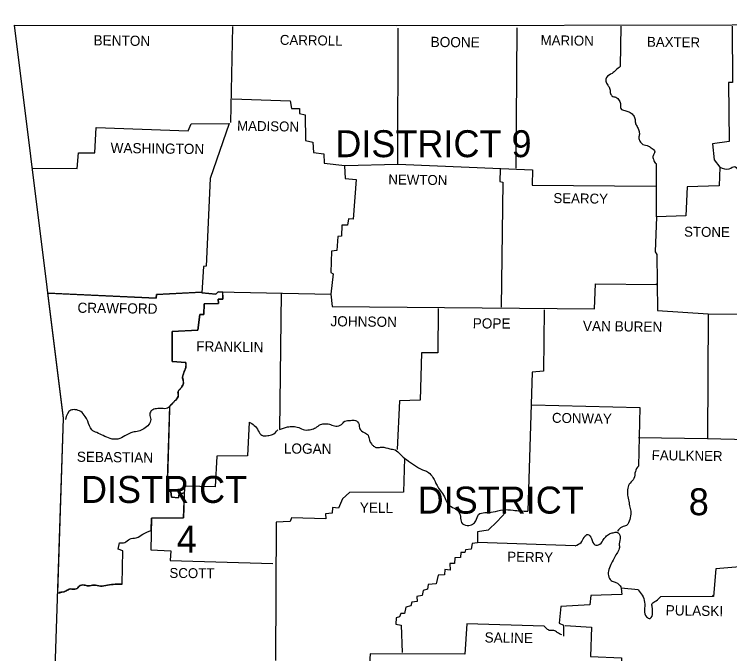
# Model space of a CAD drawing. Extents: x -17668 to 16999, y -17303 to 5867.
# Drawn here: x 1332 to 2998, y 4379 to 5867 of the extents above; entities that cross this region are included whole.
import ezdxf

# ---------------------------------------------------------------- set-up
doc = ezdxf.new("R2010")
doc.units = 0
for name, color, linetype in [('1', 7, 'Continuous'), ('2', 7, 'Continuous'), ('3', 7, 'Continuous'), ('45', 7, 'Continuous')]:
    doc.layers.add(name, color=color, linetype=linetype)

msp = doc.modelspace()

# ---------------------------------------------------------------- linework, layer by layer
at = {"layer": '1'}
for points in [[(1332.2, 5841.4), (2222.1, 5840.9), (3003, 5842.5), (3924.3, 5856.8), (4351.4, 5866.7)], [(1332.2, 5841.4), (1446.1, 4926.7), (1396.6, 3433.6)], [(1840.1, 5838.1), (1835.2, 5615.2)], [(1839, 5669.7), (1974.4, 5665.3), (1977.7, 5647.7), (1996.4, 5647.2), (1995.9, 5636.1), (2009.1, 5632.8), (2010.2, 5572.9), (2027.3, 5569), (2028.4, 5545.3), (2052.6, 5542), (2053.7, 5520), (2101.6, 5515.1), (2224.8, 5517.8), (2225.9, 5834.3)], [(2501.7, 5835.4), (2500, 5508.5)], [(2743.8, 5839.2), (2742.7, 5745.1)], [(3003, 5839.2), (3004.1, 5708.2), (2994.8, 5707.7), (2996.4, 5570.7), (2957.9, 5565.2), (2961.2, 5528.3), (2974.4, 5511.2), (2973.3, 5467.7), (2898.5, 5465), (2895.7, 5397.8), (2827.5, 5395.6), (2824.2, 5314.2), (2828, 5307.6), (2829.7, 5177.7), (2947.5, 5170), (2945.8, 4880), (3039.4, 4877.2), (3039.4, 4582.2), (2965.6, 4576.7), (2960.1, 4511.8), (2836.3, 4511.2)], [(1375.6, 5508.5), (1478.6, 5507.9), (1481.3, 5544.2), (1519.3, 5544.2), (1522.6, 5603.1), (1737.2, 5595.4), (1743.8, 5611.9), (1832.4, 5612.5), (1787.9, 5484.8), (1779.1, 5280.6), (1772.4, 5280.1), (1769.1, 5218.4), (1801.6, 5215.7), (1806.6, 5220.6), (2069.1, 5215.7), (2071.8, 5186.5)], [(2100.5, 5514), (2102.7, 5484.3), (2128, 5482.6), (2121.4, 5390.1), (2109.8, 5390.7), (2107.6, 5375.8), (2094.4, 5375.8), (2093.9, 5350.5), (2085.6, 5350), (2082.8, 5317.5), (2070.7, 5315.8), (2069.1, 5266.3), (2074.6, 5262.5), (2069.1, 5215.7)], [(2224.8, 5517.8), (2538.5, 5504.6), (2538, 5468.8), (2825.8, 5466.6)], [(2827.5, 5395.6), (2826.9, 5519.5)], [(2463.1, 5506.3), (2462.6, 5477.6), (2469.7, 5476), (2465.3, 5185.4)], [(2071.8, 5186.5), (2682.7, 5181.6), (2685.5, 5239.3), (2827.5, 5237.7)], [(2825.8, 5238.2), (2827.5, 5239.9)], [(1412, 5217.9), (1662.4, 5206.3), (1663.5, 5215.1), (1768, 5220.1)], [(1817.6, 5213.5), (1817.6, 5203.6), (1807.1, 5203.6), (1807.7, 5193.7), (1774.1, 5193.1), (1773.5, 5168.3), (1764.2, 5168.3), (1759.2, 5131.5), (1699.8, 5128.7), (1699.3, 5058.8), (1731.2, 5056.6)], [(1953.5, 5217.9), (1949.7, 4900.3)], [(2318.9, 5182.1), (2318.4, 5079.2), (2280.4, 5078.6), (2277.1, 4969.1), (2228.7, 4967.5), (2223.2, 4854.1)], [(2565.5, 5179.4), (2564.4, 5036.3), (2538, 5034.1), (2527.5, 4710.5)], [(2947.5, 5170), (3230.3, 5168.3), (3254.6, 5179.9), (3252.9, 4964.7), (3236.4, 4957.6), (3221.5, 4944.9), (3216.6, 4940), (3216, 4878.3), (3036.1, 4878.3)], [(1693.7, 4947.7), (1688.2, 4758.3), (1696.5, 4756.1), (1698.1, 4742.9), (1714.7, 4741.8), (1716.3, 4751.2), (1729.5, 4753.4)], [(2536.9, 4957.6), (2788.4, 4951.5), (2785.1, 4815.6)], [(1878.7, 4917.9), (1874.8, 4839.2), (1803.3, 4838.7), (1799.4, 4767.1), (1728.4, 4768.8), (1726.2, 4695), (1651.9, 4694.5), (1649.7, 4620.7), (1696.5, 4618), (1694.8, 4595.4), (1933.7, 4588.8)], [(2785.6, 4882.2), (2945.8, 4880)], [(2240.2, 4833.7), (2238, 4754.5), (2112.6, 4753.9), (2096.1, 4739.6), (2086.7, 4717.6), (2072.9, 4718.7), (2072.4, 4706), (2056.4, 4704.4), (2057, 4692.8), (1977.2, 4695), (1974.4, 4686.2), (1941.4, 4685.1), (1940.3, 4363.2)], [(2476.3, 4708.3), (2456.5, 4686.8), (2435.1, 4666.4), (2410.3, 4662.6), (2410.3, 4636.7), (2398.2, 4635.1), (2396, 4621.8), (2382.2, 4620.7), (2381.1, 4614.7), (2371.8, 4614.1), (2371.2, 4602.6), (2358, 4602), (2356.9, 4588.8), (2345.9, 4588.8), (2346.5, 4573.4), (2334.4, 4574.5), (2333.8, 4562.4), (2318.9, 4561.3), (2314.5, 4541.5), (2295.8, 4539.8), (2294.2, 4528.8), (2284.3, 4526.1), (2281.5, 4514.5), (2268.9, 4511.8), (2270, 4500.2), (2257.3, 4499.1), (2255.1, 4490.3), (2243.6, 4487), (2240.8, 4472.1), (2232, 4472.7), (2229.2, 4465), (2221, 4462.2), (2220.4, 4447.4), (2233.1, 4445.2), (2235.3, 4381.3)], [(1583.1, 4540.9), (1584.8, 4618.5), (1573.8, 4621.8), (1577.1, 4636.7)], [(2637.6, 4630.1), (2410.9, 4637.3)], [(2784.5, 4527.2), (2744.9, 4531.6), (2746.6, 4516.7), (2674.5, 4514), (2672.3, 4492.5), (2604.6, 4488.7), (2600.7, 4450.1), (2610.6, 4445.2), (2610.6, 4419.9)], [(2957.4, 4512.3), (2960.1, 4515.1)], [(2565.5, 4443), (2385.5, 4448.5), (2380.6, 4377.5), (2160.4, 4378.6), (2159.3, 4354.9)], [(2614.5, 4444.6), (2676.1, 4440.8), (2673.9, 4372), (2746, 4369.2), (2747.1, 4309.2), (2781.2, 4306.5), (2781.2, 4296), (2813.2, 4293.8), (2814.3, 4255.3), (2886.9, 4255.3), (2889.1, 4217.3), (2956.3, 4214), (2955.7, 4142.5)]]:
    msp.add_lwpolyline(points, dxfattribs=at)
for points in [[(2742.7, 5745.1), (2732.8, 5736.9), (2724, 5729.2), (2710.8, 5719.8), (2709.1, 5711), (2713.6, 5702.2), (2718, 5695), (2719.6, 5685.1), (2723.5, 5676.9), (2732.8, 5673.6), (2740.5, 5666.4), (2743.3, 5656.5), (2744.4, 5647.2), (2753.2, 5642.8), (2763.1, 5639.5), (2772.4, 5632.8), (2776.8, 5624.6), (2777.9, 5614.1), (2781.8, 5605.9), (2786.2, 5596), (2787.3, 5587.7), (2786.2, 5579.5), (2788.4, 5571.8), (2795.6, 5564.1), (2808.2, 5560.2), (2817, 5554.7), (2823.1, 5547), (2819.2, 5537.6), (2819.8, 5529.4), (2824.7, 5519.5)], [(2974.4, 5511.2), (2996.4, 5507.4), (3009.6, 5512.3), (3019, 5498), (3024, 5487), (3032.2, 5471), (3045.4, 5466.1), (3055.3, 5457.3), (3055.3, 5447.9), (3046.5, 5439.1), (3039.9, 5430.3), (3042.1, 5419.9), (3044.3, 5405.5), (3044.3, 5391.8), (3041, 5379.1), (3038.3, 5367.6), (3041, 5357.7), (3051.5, 5359.3), (3062.5, 5367.6), (3074, 5367.6), (3085, 5361.5), (3096.6, 5351.1), (3108.2, 5353.3), (3117.5, 5356), (3130.7, 5359.9), (3140.1, 5354.9), (3148.3, 5348.3), (3158.2, 5337.9), (3167.6, 5331.3), (3179.7, 5325.2), (3194.6, 5321.3), (3208.3, 5312), (3210.5, 5296), (3210, 5282.3), (3208.9, 5265.2), (3207.8, 5246.5), (3209.4, 5228.3), (3215.5, 5216.2), (3223.2, 5201.9), (3225.4, 5188.7), (3224.8, 5167.8)], [(1731.2, 5056.6), (1731.2, 5045.1), (1726.8, 5033), (1724, 5022.5), (1725.7, 5008.7), (1720.7, 4997.7), (1713.6, 4988.9), (1713.6, 4977.9), (1705.3, 4966.4), (1696.5, 4957.6), (1688.8, 4950.4), (1675, 4949.3), (1663.5, 4948.8), (1651.9, 4944.9), (1647.5, 4936.6), (1649.7, 4924), (1645.3, 4911.9), (1633.8, 4902.5), (1621.1, 4896.5), (1607.9, 4894.3), (1589.7, 4885.5), (1573.2, 4878.3), (1555.6, 4879.4), (1539.1, 4886.6), (1524.2, 4893.2), (1512.7, 4899.8), (1503.3, 4920.1), (1497.3, 4931.1), (1486.8, 4942.2), (1474.2, 4946.6), (1463.7, 4945.5), (1451, 4924)], [(1878.7, 4917.9), (1890.8, 4910.2), (1900.1, 4897.6), (1908.4, 4887.1), (1922.1, 4886.6), (1933.2, 4888.8), (1945.8, 4899.8)], [(1949.7, 4900.3), (1967.8, 4906.4), (1981, 4907.5), (1994.2, 4905.3), (2008, 4899.8), (2022.9, 4900.9), (2033.9, 4904.7), (2044.9, 4911.9), (2057, 4914.1), (2068.5, 4911.9), (2080.6, 4908.6), (2093.9, 4912.4), (2101.6, 4919.6), (2114.8, 4921.8), (2126.3, 4921.8), (2134.6, 4912.4), (2136.2, 4902.5), (2146.7, 4893.2), (2156, 4887.1), (2158.8, 4875.6), (2163.7, 4867.3), (2168.7, 4861.8), (2175.9, 4858.5), (2188, 4859.6), (2206.7, 4855.7), (2218.8, 4853), (2229.8, 4843.6), (2240.2, 4833.7)], [(2240.2, 4833.7), (2259.5, 4820.5), (2277.7, 4809), (2296.4, 4800.7), (2306.8, 4788.6), (2316.2, 4769.9), (2323.9, 4758.3), (2333.8, 4744), (2341, 4728.1), (2352.5, 4719.3), (2364.6, 4711.6), (2370.7, 4697.8), (2373.4, 4684), (2386.6, 4677.4), (2399.3, 4680.2), (2406.5, 4688.4), (2413.1, 4702.7), (2427.9, 4707.2), (2447.2, 4708.8), (2469.2, 4713.8), (2493.4, 4712.7), (2527.5, 4710.5)], [(2785.1, 4815.6), (2777.9, 4802.9), (2774.6, 4786.4), (2765.8, 4775.9), (2760.3, 4763.8), (2759.8, 4747.9), (2762.5, 4733.6), (2765.3, 4719.8), (2767.5, 4707.2), (2764.7, 4691.2), (2757.6, 4677.4), (2746.6, 4673.6), (2736.1, 4664.2)], [(1577.1, 4636.7), (1589.2, 4637.8), (1600.7, 4645.5), (1616.1, 4648.8), (1631.6, 4657.1), (1650.8, 4665.9)], [(2637.6, 4630.1), (2651.4, 4637.8), (2658.5, 4649.4), (2667.3, 4656.5), (2676.1, 4646.6), (2683.8, 4632.3), (2692.1, 4632.3), (2702.5, 4642.2), (2709.1, 4651), (2717.4, 4657.6), (2726.2, 4660.4), (2735.6, 4661.5), (2742.7, 4651), (2740.5, 4634.5), (2740.5, 4623.5), (2734.5, 4611.9), (2727.9, 4599.8), (2720.7, 4586.1), (2715.2, 4571.2), (2716.3, 4556.9), (2724, 4547.5), (2732.8, 4544.8), (2744.9, 4532.7)], [(1583.1, 4540.9), (1567.2, 4540.4), (1549, 4538.2), (1532.5, 4536), (1517.6, 4538.7), (1503.9, 4536.5), (1494.5, 4538.7), (1483, 4536), (1476.4, 4529.4), (1462.6, 4529.4), (1452.7, 4525), (1436.7, 4521.1)], [(2784.5, 4527.2), (2793.9, 4515.1), (2799.4, 4498.6), (2799.4, 4479.9), (2803.8, 4464.4), (2812.6, 4461.1), (2818.1, 4474.4), (2817, 4487.6), (2817, 4495.3), (2826.4, 4501.9), (2836.3, 4511.2)], [(2606.8, 4422.6), (2596.3, 4428.1), (2588.1, 4433.1), (2579.3, 4432.5), (2572.1, 4436.9), (2565.5, 4443)]]:
    msp.add_spline(points, degree=3, dxfattribs=at)
at = {"layer": '45'}
for points in [[(1731.2, 5056.6), (1699.3, 5058.8), (1699.8, 5128.7), (1759.2, 5131.5), (1764.2, 5168.3), (1773.5, 5168.3), (1774.1, 5193.1), (1807.7, 5193.7), (1807.1, 5203.6), (1817.6, 5203.6), (1817.6, 5220.4), (1806.6, 5220.6), (1801.6, 5215.7), (1769.1, 5218.4), (1769.2, 5220.1), (1663.5, 5215.1), (1662.4, 5206.3), (1409.8, 5218), (1446.1, 4926.7), (1432.6, 4520.1)], [(1650.8, 4665.9), (1651.9, 4694.5), (1726.2, 4695), (1728, 4753.1), (1716.3, 4751.2), (1714.7, 4741.8), (1698.1, 4742.9), (1696.5, 4756.1), (1688.2, 4758.3), (1694, 4954.7)], [(1583.1, 4540.9), (1584.8, 4618.5), (1573.8, 4621.8), (1577.1, 4636.7)]]:
    msp.add_lwpolyline(points, dxfattribs=at)
for points in [[(1694, 4954.7), (1696.5, 4957.6), (1700.9, 4961.9), (1705.3, 4966.4), (1707.7, 4969), (1709.8, 4971.9), (1711.8, 4974.9), (1712.7, 4976.4), (1713.6, 4977.9), (1714.1, 4980.5), (1713.6, 4983.4), (1713.1, 4986.3), (1713.6, 4988.9), (1715.1, 4991.2), (1717.1, 4993.3), (1719, 4995.4), (1720.7, 4997.7), (1723.6, 5003.1), (1725.7, 5008.7), (1725.8, 5010.5), (1725.7, 5012.2), (1724.9, 5015.6), (1724, 5019.1), (1724, 5022.5), (1726.8, 5033), (1727.8, 5036), (1729, 5039), (1730.2, 5042), (1731.2, 5045.1), (1731.9, 5050.8), (1731.7, 5053.7), (1731.2, 5056.6)], [(1577.1, 4636.7), (1589.2, 4637.8), (1600.7, 4645.5), (1616.1, 4648.8), (1631.6, 4657.1), (1650.8, 4665.9)], [(1432.6, 4520.1), (1452.7, 4525), (1462.6, 4529.4), (1476.4, 4529.4), (1483, 4536), (1494.5, 4538.7), (1503.9, 4536.5), (1517.6, 4538.7), (1532.5, 4536), (1549, 4538.2), (1567.2, 4540.4), (1583.1, 4540.9)]]:
    msp.add_spline(points, degree=3, dxfattribs=at)

# ---------------------------------------------------------------- texts
at = {"layer": '2'}
for s, height, rotation, p in [('BENTON', 23.67, 359.2527, (1516.5, 5794.6)), ('CARROLL', 23.11, 359.1481, (1950.2, 5795.8)), ('BOONE', 23.67, 359.4001, (2301.3, 5790.8)), ('MARION', 23.11, 359.1854, (2557.3, 5795.2)), ('BAXTER', 23.11, 359.2559, (2804.9, 5791.3)), ('MADISON', 23.11, 359.0906, (1850.6, 5596)), ('WASHINGTON', 23.66, 359.232, (1556.2, 5544.2)), ('NEWTON', 23.11, 359.2717, (2202.8, 5471)), ('SEARCY', 23.11, 359.2527, (2587, 5427.6)), ('STONE', 23.11, 359.4001, (2891.3, 5349.4)), ('CRAWFORD', 23.66, 359.2771, (1479.1, 5172.2)), ('JOHNSON', 23.67, 359.3514, (2068, 5140.8)), ('POPE', 23.67, 359.6155, (2399.3, 5135.9)), ('VAN BUREN', 23.67, 359.3508, (2655.8, 5129.8)), ('FRANKLIN', 23.67, 359.1815, (1755.4, 5082.5)), ('CONWAY', 23.11, 359.0371, (2583.7, 4916.3)), ('LOGAN', 23.67, 359.3969, (1959.6, 4844.7)), ('SEBASTIAN', 23.66, 359.2816, (1477.5, 4825.5)), ('FAULKNER', 23.11, 359.2486, (2815.9, 4829.3)), ('YELL', 23.67, 359.1987, (2136.2, 4707.2)), ('PERRY', 23.11, 359.0858, (2479.7, 4593.2)), ('SCOTT', 23.11, 359.4063, (1693.2, 4555.3)), ('PULASKI', 23.67, 359.053, (2848.4, 4468.3)), ('SALINE', 23.67, 359.1491, (2426.8, 4405))]:
    msp.add_text(s, height=height, rotation=rotation, dxfattribs=at).set_placement(p)
at = {"layer": '3'}
for s, height, p in [('DISTRICT 9', 62.74, (2079.5, 5534.3)), ('DISTRICT', 62.74, (1487.4, 4729.7)), ('DISTRICT', 62.74, (2271.1, 4704.9)), ('8', 62.7, (2902.3, 4701.1)), ('4', 62.7, (1710.3, 4614.1))]:
    msp.add_text(s, height=height, dxfattribs=at).set_placement(p)

doc.saveas('drawing.dxf')
